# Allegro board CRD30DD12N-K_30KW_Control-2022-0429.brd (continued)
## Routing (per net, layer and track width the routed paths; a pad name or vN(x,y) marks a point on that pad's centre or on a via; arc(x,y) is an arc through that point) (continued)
P_SDA: length 24.7
  ART03 w0.127: v1(63.5,34.29) 62.61,34.29 56.74,40.16 47.2,40.16 v1(46.71,40.64)
  BOTTOM w0.152: U32.5 64.14,33.66 v1(63.5,34.29) 63.5,34.67 64.26,35.44 R437.1 ; U28.173 v1(46.71,40.64)
P_WD_GREEN: length 13.2
  TOP w0.152: D102.2 41.73,43.25 41.02,42.55 v1(40.64,42.55)
  BOTTOM w0.152: v1(40.64,42.55) 40.31,42.87 34.48,42.87 32.55,40.93 32.55,40.46 31.71,39.63 U28.143
P_WD_RED: length 17.2
  TOP w0.152: v1(44.7,42.29) 45.5,42.29 45.72,42.51 D103.2
  BOTTOM w0.152: U28.144 32.22,39.56 33.08,40.42 33.08,40.83 34.51,42.26 39.91,42.26 40.13,42.04 41.55,42.04 42.19,42.67 44.32,42.67 v1(44.7,42.29)
PCS_ADC1: length 11.4
  BOTTOM w0.152: C703.1 R706.2 58.54,24.25 56.05,21.76 52.91,21.76 52.39,22.28 U28.30
RLYCTRL11: length 3.9
  TOP w0.152: v1(28.07,40.64) 27.94,40.51 R703.2
  BOTTOM w0.152: v1(28.07,40.64) 27.69,40.64 26.71,39.67 U28.133
RLYCTRL22: length 38.7
  ART03 w0.127: v1(57.63,30.66) 53.42,30.66 52.7,31.37 52.7,32.13 52.44,32.4 32.37,32.4 v1(28.96,35.81)
  BOTTOM w0.152: v1(57.63,30.66) 57.1,31.19 57.1,32.05 56.77,32.38 R704.2 ; U28.132 26.21,36.79 27.18,35.81 v1(28.96,35.81)
SA_ADC: length 57.8
  TOP w0.152: D124.3 v1(25.4,41.53)
  ART03 w0.127: v1(46.08,19.3) 45.68,19.7 31.06,19.7 29.55,21.21 29.55,33.93 26.92,36.56 26.92,39.12 25.4,40.64 v1(25.4,41.53)
  BOTTOM w0.152: v1(46.08,19.3) 46.08,19.12 48.41,16.79 U28.41 57.47,16.79 57.99,16.26 58.93,16.26 ; R713.2 C706.1 58.93,16.26 ; 58.93,16.26 R712.1
SA_ADC1: length 10.4
  BOTTOM w0.152: U28.40 55.64,17.28 55.64,17.28 57.6,17.28 58.23,17.9 R712.2 C705.1
SB_ADC: length 54.1
  TOP w0.152: R719.2 C708.1 49.41,15.63 R718.1 48.98,15.75 48.78,15.95 48.78,17.68 v1(48.35,18.11) ; D125.3 v1(22.23,41.53)
  ART03 w0.127: v1(22.23,41.53) 22.61,41.15 24.26,41.15 26.49,38.91 26.49,36.59 29.05,34.03 29.05,21.18 31.01,19.22 44.62,19.22 45.18,18.66 47,18.66 47.54,18.11 v1(48.35,18.11)
  BOTTOM w0.152: v1(48.35,18.11) 48.37,18.09 48.37,18.02 48.61,17.79 U28.39
SB_ADC1: length 5
  TOP w0.152: R718.2 C707.1 51.36,17.27 v1(52.12,18.03)
  BOTTOM w0.152: U28.38 51.87,18.28 v1(52.12,18.03)
SC_ADC: length 57.8
  TOP w0.152: R724.1 47.62,14.65 48,15.03 C710.1 R725.2 48,17.64 47.54,18.11 v1(46.09,18.11) ; D126.3 v1(19.05,41.53)
  ART03 w0.127: v1(46.09,18.11) 46.06,18.07 45.04,18.07 44.45,18.67 30.86,18.67 28.51,21.02 28.51,34.17 26.11,36.57 26.11,38.79 24.26,40.64 19.94,40.64 v1(19.05,41.53)
  BOTTOM w0.152: U28.48 46.71,17.63 46.24,18.11 v1(46.09,18.11)
SC_ADC1: length 4.4
  TOP w0.152: R724.2 C709.1 v1(46.35,11.43)
  BOTTOM w0.152: U28.49 46.22,11.57 v1(46.35,11.43)
SCS_A: length 74.7
  TOP w0.635: v1(45.72,52.2) R715.2 R716.2 R714.2 36.32,50.93 J2.2
  ART03 w0.127: v1(61.34,24.13) 61.72,24.51 61.72,26.71 62.74,27.72 62.74,28.96 64.75,30.97 64.75,31.89 70.48,37.63 70.48,40.47 66.46,44.5 53.42,44.5 v1(45.72,52.2)
  BOTTOM w0.152: v1(61.34,24.13) 61.98,23.5 61.98,21.13 62.29,20.82 62.29,19.88 61.48,19.07 61.48,17.39 62.32,16.55 62.32,14.19 61.46,13.34 R713.1
SCS_B: length 102.9
  TOP w0.152: v1(51.82,15) 51.69,14.88 51.69,12.85 51.54,12.7 R719.1
  TOP w0.635: J2.8 26.04,48.27 R722.2 R721.2 R720.2 31.39,45.85 31.9,46.35 v1(32.77,46.35)
  ART03 w0.127: v1(32.77,46.35) 36.4,46.35 38.95,43.8 66.45,43.8 70.1,40.15 70.1,37.83 61.72,29.45 61.72,27.3 61.28,26.86 61.28,24.91 60.82,24.45 60.82,21.59 61.28,21.12 61.93,21.12 63.2,19.84 63.2,11.22 62.18,10.2 56.82,10.2 53.01,14.01 52.81,14.01 v1(51.82,15)
SCS_C: length 89.6
  TOP w0.152: R725.1 v1(45.08,17.14)
  TOP w0.635: v1(62.36,46.23) 63.76,46.23 R728.2 R727.2 R726.2 69.22,47.82 68.59,48.45 68.59,51.44 J3.10
  ART03 w0.127: v1(62.36,46.23) 65.56,46.23 70.99,40.79 70.99,37.67 65.61,32.29 65.61,29.92 62.07,26.38 62.07,22 63.63,20.45 63.63,11.05 62.43,9.85 56.57,9.85 52.83,13.59 42.96,13.59 42.29,14.26 42.29,15.86 43.58,17.14 v1(45.08,17.14)
SCS_RTN_A: length 15.7
  TOP w0.635: R711.1 46.98,48.13 R715.1 R716.1 R714.1 35.06,48.13 J2.4
SCS_RTN_B: length 15.9
  TOP w0.635: R717.1 32.38,43.05 R720.1 R721.1 R722.1 24.98,43.05 24.59,43.43 24.59,49.37 J2.10
SCS_RTN_C: length 19.3
  TOP w0.635: R723.1 62.87,43.05 R728.1 R727.1 R726.1 70.79,43.05 71.29,43.55 71.29,51.28 J3.12
SR-PWM-A: length 42.3
  TOP w0.152: U59.12 63.91,22.23 v1(63.25,22.89)
  ART03 w0.127: v1(63.25,22.89) 62.52,23.61 62.52,26.37 66.63,30.48 66.63,32.83 71.34,37.53 71.34,41.21 65.34,47.21 60.11,47.21 J3.1
SR-PWM-AA: length 45.3
  TOP w0.152: 65.12,23.5 64.54,23.5 63.9,24.14 63.9,25.76 63.12,26.54 58.29,26.54 v1(57.53,25.78) ; R422.2 40.01,42.19 v1(39.47,41.66)
  ART03 w0.127: v1(39.47,41.66) 39.88,41.66 40.64,40.89 40.64,40.13 43.43,37.34 49.02,37.34 50.8,35.56 50.8,34.8 51.94,33.66 52.32,33.66 52.7,33.27 52.7,32.77 53.09,32.38 56.64,32.38 58.17,30.86 58.17,26.42 v1(57.53,25.78)
  BOTTOM w0.152: v1(39.47,41.66) 39.47,40.32 40.22,39.58 U28.160
SR-PWM-B: length 39.9
  TOP w0.152: 59.59,23.5 61.59,23.5 v1(63.25,25.15)
  ART03 w0.127: v1(63.25,25.15) 63.25,26.44 67.58,30.78 67.58,33.26 71.7,37.38 71.7,41.61 65.27,48.04 61.82,48.04 J3.3
SR-PWM-BB: length 40.2
  TOP w0.152: v1(43.69,41.78) 43.31,41.4 43.31,40.26 43.56,40.01 43.56,38.1 43.43,37.98 R423.2 ; v1(59.87,25.91) 60.71,25.91 60.83,25.78 60.83,24.89 60.71,24.77 U59.1
  ART03 w0.127: v1(59.87,25.91) 59.82,25.96 59.82,32 55.5,36.32 52.96,36.32 52.7,36.58 52.7,38.23 52.07,38.86 44.58,38.86 43.05,40.39 43.05,41.15 v1(43.69,41.78)
  BOTTOM w0.152: v1(43.69,41.78) 43.22,41.31 U28.166
SR-PWM-C: length 41
  TOP w0.152: v1(63.25,24.13) 62.74,23.62 62.74,21.59 62.1,20.95 U59.4
  ART03 w0.127: v1(63.25,24.13) 64.77,25.65 64.77,27.36 68.65,31.23 68.65,33.95 72.07,37.38 72.07,42.12 65.31,48.89 63.52,48.89 J3.5
SR-PWM-CC: length 25.5
  TOP w0.152: v1(52.07,36.83) R424.2 ; U59.3 v1(57.91,22.23)
  ART03 w0.127: v1(52.07,36.83) 52.07,36.22 52.73,35.56 55.67,35.56 59.23,32 59.23,23.54 v1(57.91,22.23)
  BOTTOM w0.152: U28.4 50.91,35.28 52.07,36.45 v1(52.07,36.83)
SR-PWM-D: length 41
  TOP w0.152: U59.6 60.81,18.41 60.96,18.57 60.96,18.67 63.5,21.21 v1(63.5,21.59)
  ART03 w0.127: v1(63.5,21.59) 63.87,21.96 63.87,21.98 66.04,24.14 66.04,28.13 69.56,31.65 69.56,34.36 72.46,37.25 72.46,42.49 J3.7
SR-PWM-DD: length 30.5
  TOP w0.152: U59.5 58.29,19.68 57.91,20.07 v1(57.91,21.21) ; R425.2 v1(53.34,33.02)
  ART03 w0.127: v1(53.34,33.02) 56.64,33.02 58.72,30.94 58.72,23.79 57.4,22.48 57.4,21.72 v1(57.91,21.21)
  BOTTOM w0.152: v1(53.34,33.02) 53.34,32.77 52.8,32.23 52.8,26.47 52.47,26.14 51.5,26.14 51.36,26.28 U28.22
SR-PWM-E: length 41.9
  TOP w0.152: v1(66.8,16.26) 66.8,16.76 66.42,17.14 U59.8
  ART03 w0.127: J3.9 72.84,44.64 72.84,33.35 67.35,27.86 67.35,23.92 65.79,22.35 65.79,17.27 v1(66.8,16.26)
SR-PWM-EE: length 30.8
  TOP w0.152: U59.9 62.99,18.41 v1(62.23,17.65) ; R610.2 53.85,31.11 52.7,31.11 v1(51.94,31.88)
  ART03 w0.127: v1(51.94,31.88) 51.82,31.88 50.67,30.73 50.67,29.34 51.41,28.6 52.81,28.6 55.75,25.65 55.75,20.57 57.28,19.05 60.83,19.05 v1(62.23,17.65)
  BOTTOM w0.152: U28.10 51.54,32.28 v1(51.94,31.88)
SR-PWM-F: length 36.2
  TOP w0.152: v1(66.67,19.68) U59.10
  ART03 w0.127: v1(66.67,19.68) 68.56,21.57 68.56,28.39 73.24,33.07 73.24,46.79 J3.11
SR-PWM-FF: length 26.2
  TOP w0.152: v1(51.94,30.79) 51.64,30.48 R611.2 ; U59.11 63.93,20.95 62.23,19.25 v1(62.23,18.8)
  ART03 w0.127: v1(51.94,30.79) 51.31,30.15 51.31,29.59 51.88,29.02 53.02,29.02 56.39,25.65 56.39,21.59 57.53,20.45 60.58,20.45 v1(62.23,18.8)
  BOTTOM w0.152: U28.13 v1(51.94,30.79)
TCK_P: length 8.6
  TOP w0.152: v1(29.86,11.54) 31.87,11.54 33.05,10.36 33.05,9.63 33.66,9.02 R408.2 R407.2
  BOTTOM w0.152: U28.81 30.22,11.82 29.94,11.54 v1(29.86,11.54)
TDI_P: length 18.1
  TOP w0.152: R405.2 v1(29.84,6.35) 29.2,5.7 28.44,5.7 27.92,5.18 27.92,3.2 J5.3
  BOTTOM w0.152: U28.77 32.22,11.36 33.04,10.54 33.04,8.95 32.52,8.44 32.52,6.2 32.14,5.82 30.38,5.82 v1(29.84,6.35)
TDO_P: length 13.9
  TOP w0.152: J5.7 33.01,3.19 33.01,5.09 v1(31.75,6.35) 32.38,6.99 R406.2
  BOTTOM w0.152: U28.78 31.71,6.39 v1(31.75,6.35)
TMS_P: length 15.7
  TOP w0.152: R404.2 v1(26.04,6.35) 25.18,5.5 25.18,3.39 J5.1
  BOTTOM w0.152: v1(26.04,6.35) 29.24,9.56 29.24,10.44 29.67,10.87 30.07,10.87 30.71,11.51 U28.80
VO1+: length 16.3
  BOTTOM w0.508: R574.1 90.05,41.41 J4.1
VO2+: length 11.9
  TOP w0.508: R573.1 88.27,45.73 J4.3
VP3.3A: length 45.8
  TOP w0.381: v1(48.26,19.28) 48.49,19.05 C521.1
  TOP w0.508: C550.2 v1(43.81,15.24) ; D128.2 60.64,6.66 v1(60.33,6.35) ; v1(54.29,6.05) D89.2 ; D127.2 42.86,6.65 42.35,6.15 v1(41.72,6.15)
  ART03 w0.381: v1(34.19,6.25) 35.05,7.11 40.75,7.11 v1(41.72,6.15) 42.5,6.15 43.18,5.46 50.8,5.46 v1(51.44,6.1) 52.11,6.77 53.57,6.77 v1(54.29,6.05)
  BOTTOM w0.254: v1(43.81,15.24) 43.71,15.14 U28.54 ; v1(48.26,19.28) U28.36
  BOTTOM w0.381: v1(34.19,6.25) 33.72,6.25 33.34,6.63 D86.2 ; v1(54.29,6.05) 55.51,4.83 56.44,4.83
  BOTTOM w0.508: v1(41.72,6.15) 40.96,6.9 D90.2 ; v1(51.44,6.1) 51.64,6.1 52.39,6.85 D115.2 ; D85.2 53.66,23.18 v1(52.96,22.48) ; D92.2 v1(57.47,18.1)
  vias: v1(60.83,10.79) v1(61.85,10.79)
VP3.3D: length 171.2
  TOP w0.152: D104.2 49.53,43.18
  TOP w0.381: v1(26.67,16.51) 26.67,16.63 C540.1 ; R411.1 R412.1 47.11,2.03 48.39,0.76 63.88,0.76 ; v1(26.35,40.64) D124.2 ; C541.2 v1(27.94,15.24) ; D95.2 v1(16.82,39.5) ; D126.2 v1(20,39.5) ; D125.2 v1(23.17,39.5)
  TOP w0.508: C542.2 v1(29.84,15.24) ; C536.1 v1(26.67,28.57) ; v1(44.2,36.83) 44.32,36.96 C523.2 ; C552.1 C557.2 v1(48.26,24.13) ; 49.53,43.18 v1(49.53,41.91) v1(51.44,41.91) 50.92,41.4 C520.1 ; C534.1 v1(26.67,31.11) ; v1(39.37,15.24) 38.61,15.24 38.23,14.86 C547.2 ; C555.2 v1(48.26,27.94) ; C553.2 49.28,33.02 48.26,32 v1(48.26,31.75) ; C524.2 v1(40.01,36.83) ; v1(12.24,30.89) 12.7,31.35 R691.1 R537.2 ; R327.2 v1(31.75,40.64) ; R409.2 v1(31.11,10.16) ; C528.2 v1(33.66,36.83) ; C539.1 v1(26.67,20.32) ; C544.2 v1(33.66,15.24) ; v1(29.59,36.83) 30.48,37.72 C529.2 ; J17.2 77.91,8.41 R598.1 ; C538.1 v1(26.67,23.5) ; v1(36.2,10.16) 35.94,9.91 35.94,8 35.43,7.5 R407.1 ; C533.1 26.16,32.38 v1(26.67,32.89) ; C545.2 v1(34.92,15.24) ; C546.2 v1(36.83,15.24) ; R404.1 v1(26.04,10.16) ; R406.1 v1(32.38,10.16) ; C537.1 v1(26.67,27.3) ; v1(34.92,36.83) C527.2 ; C531.1 v1(26.67,34.92) ; R405.1 v1(29.84,10.16) ; R400.2 v1(37.47,40.64) ; R540.1 5.59,21.82
  ART03 w0.508: v1(26.35,40.64) 26.35,42.55 ; v1(4.19,47.62) 7.38,44.43 7.38,39.35 10.72,36.02 10.72,33.26 12.24,31.74 v1(12.24,30.89)
  BOTTOM w0.254: v1(26.67,27.3) 26.19,27.79 U28.114 ; U28.127 26.03,34.28 v1(26.67,34.92) ; 48.26,29.79 U28.15 ; v1(33.66,15.24) 33.22,14.8 U28.75 ; U28.26 48.41,24.28 v1(48.26,24.13) ; U28.68 36.71,15.12 v1(36.83,15.24) ; U28.159 39.71,37.12 v1(40.01,36.83) ; U28.91 26.44,16.28 v1(26.67,16.51) ; U28.119 26.22,30.28 26.67,30.73 v1(26.67,31.11) 26.04,31.11 25.71,30.79 U28.120 ; U28.11 48.3,31.79 v1(48.26,31.75) ; U28.3 48.49,35.79 ; U28.106 26.38,23.79 v1(26.67,23.5) ; U28.116 26.46,28.79 v1(26.67,28.57) ; U28.125 26.28,33.28 v1(26.67,32.89) ; v1(34.92,36.83) 35.23,36.83 36.22,37.82 U28.152 ; v1(34.92,15.24) 34.71,15.03 U28.72 ; v1(48.26,27.94) 48.92,27.28 U28.20 ; v1(26.67,15.24) 26.71,15.2 U28.88 ; v1(29.84,15.24) 29.71,15.11 U28.82 ; v1(33.66,36.83) 33.71,36.89 U28.147 ; v1(44.2,36.83) 44.22,36.85 U28.168 ; v1(39.37,15.24) 39.71,14.9 U28.62 ; U28.99 26.63,20.28 v1(26.67,20.32) ; U28.138 29.22,37.21 v1(29.59,36.83)
  BOTTOM w0.381: v1(19.18,27.94) R546.2
  BOTTOM w0.508: J17.2 78.11,8.22 C405.1 ; R437.2 R438.2 v1(66.67,38.1) ; v1(71.37,33.02) 72.01,32.38 R505.1 ; v1(67.94,38.1) 67.94,37.59 R439.2 ; v1(71.37,34.29) 71.88,34.29 R502.1 ; v1(70.8,29.81) 70.8,29.94 70.14,30.6 C396.1 68.96,30.6 67.94,31.62 67.94,33.18
  vias: v1(3.17,47.62) v1(3.17,46.35) v1(3.17,45.09) v1(3.17,43.81) v1(5.43,21.66) v1(6.35,11.43) v1(6.35,10.16) v1(6.35,8.89) v1(7.62,11.43) v1(7.62,10.16) v1(7.62,8.89) v1(27.94,16.51) v1(29.84,16.51) v1(52.7,41.91) v1(53.98,41.91) v1(66.04,5.08) v1(67.31,5.08) v1(68.58,5.08) v1(69.85,5.08) v1(71.75,1.27) v1(73.03,1.27) v1(74.3,1.27)
VP+5V: length 55.3
  TOP w0.381: v1(69.22,26.42) 68.58,27.05 56.58,27.05 55.88,26.35 U55.1 53.66,26.35 53.34,26.67 53.34,27.56 53.72,27.94 C494.1 ; R549.2 v1(70.48,33.02)
  TOP w0.508: R536.2 9.01,30.86 v1(9.02,30.86) ; R550.2 69.34,26.29 v1(69.22,26.42)
  ART03 w0.508: 77.35,9.78 77.35,24.94 75.01,27.28 v1(72.27,27.28)
  BOTTOM w0.508: v1(69.22,26.42) 69.85,25.78 R595.2 70.87,25.52 71.38,26.04 R594.2 v1(72.27,27.28) 72.27,29.57 71.18,30.65 71.18,32.08 70.48,32.77 v1(70.48,33.02)
  vias: v1(6.1,32.77) v1(6.1,31.62) v1(6.1,30.48) v1(7.74,30.86) v1(10.29,30.86) v1(11.3,30.86) v1(52.7,5.08) v1(53.98,5.08) v1(53.98,3.81)
VS+5V: length 42.7
  TOP w0.508: v1(95.89,23.75) 95.89,23.6 95.4,23.12 R493.1 ; R496.1 v1(92.59,34.42) ; R507.1 v1(97.91,32.26) ; v1(98.3,23.75) 97.91,24.13 R492.2
  ART03 w0.508: v1(91.56,38.1) 91.56,40.22 96.45,45.11 96.45,52.76 95.19,54.02 85.13,54.02 J4.4
  BOTTOM w0.508: v1(92.71,32.38) 92.08,33.02 R503.1 ; R569.1 v1(88.9,35.56) ; R500.1 v1(91.56,38.1) R597.1 ; R593.2 91.87,26.04 v1(92.53,26.7) ; R592.2 v1(88.9,20.95)
XCLK: length 4.6
  TOP w0.152: Y3.3 21.68,32.35 C712.1 22.86,32.38 v1(22.86,32.38)
  BOTTOM w0.254: v1(22.86,32.38) 22.96,32.28 U28.123
XRS: length 22.3
  TOP w0.381: v1(15.49,29.84) 11.68,29.84 10.92,29.08 R547.1
  TOP w0.508: R541.1 10.29,23.5 10.29,24.43 11.18,25.32 11.18,27.74 10.92,28 R547.1
  BOTTOM w0.254: C519.1 23.5,33.02 23.73,32.79 U28.124
  BOTTOM w0.381: C519.1 21.08,33.02 R546.1 17.53,33.02 15.49,30.99 v1(15.49,29.84)
N16779815: length 3.9
  TOP w0.152: R327.1 31.75,37.92 v1(30.66,36.83)
  BOTTOM w0.152: v1(30.66,36.83) 29.71,37.77 U28.139
N16833081: length 2
  TOP w0.152: R443.1 43.57,45.45 D102.1
N16833084: length 2
  TOP w0.152: D103.1 47.28,45.55 R444.1
N16833087: length 2
  TOP w0.152: D104.1 51.09,45.55 R445.1
N16835391: length 39
  TOP w0.152: v1(68.58,12.7) 73.03,8.26 J17.1
  BOTTOM w0.152: R447.1 59.05,28.2 62.7,24.55 62.7,21.5 63.32,20.88 63.32,16.27 63.91,15.68 67.5,15.68 68.58,14.61 v1(68.58,12.7) ; R446.1 C407.1 J17.1
N16848574: length 4.1
  BOTTOM w0.508: U43.2 88.01,24.77 88.14,24.64 89.92,24.64 R482.2 C446.1
N16848598: length 4.6
  BOTTOM w0.381: R593.1 C445.2
  BOTTOM w0.508: C445.2 89.41,27.3 88.14,26.04 U43.1
N16848614: length 4.9
  TOP w0.508: v1(74.93,25.4) 75.44,24.89 C447.2
  BOTTOM w0.152: U43.8 75.39,26.04 74.93,25.58 v1(74.93,25.4) 74.3,26.04 R594.1
N16848642: length 2.8
  BOTTOM w0.152: R483.1 U43.7
N16848644: length 15.1
  TOP w0.152: v1(71.12,21.08) 71.12,19.68 67.18,15.75 65.91,15.75 v1(65.41,16.26)
  BOTTOM w0.152: v1(65.41,16.26) U45.3 ; v1(71.12,21.08) 72.26,22.23 C448.2 R484.2 R483.2
N16848814: length 4.9
  BOTTOM w0.152: R485.1 74.52,20.95 74.68,21.11 74.68,22.99 75.18,23.5 76.54,23.5
N16848816: length 8.1
  BOTTOM w0.152: R485.2 72.27,19.61 71.83,19.17 R486.1 C449.1 69.22,19.17 68.98,19.42 67.17,19.42 66.67,18.92 U45.2
N16848832: length 28.9
  TOP w0.152: v1(54.86,8.94) 54.86,8.52 55.25,8.13 R487.1
  ART03 w0.127: v1(54.86,8.94) 54.95,8.94 55.04,8.86 67.24,8.86 70.48,12.1 70.48,15.88 v1(69.85,16.51)
  BOTTOM w0.152: 67.94,18.25 67.94,17.23 68.67,16.51 v1(69.85,16.51) C449.2 R486.2
N16848970: length 3.4
  BOTTOM w0.152: U44.7 95.25,20.45 95.5,20.19 96.22,20.19 96.52,20.5 U44.6
N16848978: length 9.7
  TOP w0.152: C454.1 R488.2 C453.2 R489.2 R492.1 96.4,24.25 v1(96.9,23.75)
  BOTTOM w0.152: U44.3 96.52,24.03 96.8,23.75 v1(96.9,23.75)
N16848994: length 10.6
  TOP w0.152: R493.2 R494.2 ; R494.2 93.07,24.64 v1(92.71,24.99) 91.97,24.25 R491.1 C455.1 ; R494.2 93.47,24.76 C454.2
  BOTTOM w0.152: v1(92.71,24.99) 94.59,24.99 95.25,25.66 U44.2
N16849016: length 4.4
  BOTTOM w0.152: U44.8 93.98,22.07 93.83,22.23 C457.1 R592.1
N16851028: length 3.3
  BOTTOM w0.152: U45.7 66.67,24.61 66.52,24.77 65.56,24.77 65.41,24.61 U45.6
N16851046: length 4.3
  BOTTOM w0.152: C451.1 R595.1 69.21,24.01 68.83,24.38 68.2,24.38 67.94,24.13 67.94,23.66
N16853569: length 5.3
  TOP w0.152: v1(95.89,34.29) 95.76,34.41 R495.2 C458.1 C460.1
  BOTTOM w0.152: U48.3 v1(95.89,34.29)
N16853931: length 10.1
  TOP w0.152: C460.2 97.28,38.61 96.82,39.07 94.51,39.07 94.1,38.66 R497.1 C459.1 R496.2 94.1,34.8 v1(94.61,34.29)
  BOTTOM w0.152: U48.2 v1(94.61,34.29)
N16853972: length 12.8
  TOP w0.152: C714.2 89.41,30.99 88.65,30.99 88.27,31.37 88.27,33.66 v1(88.9,34.29)
  BOTTOM w0.152: U48.1 93.18,35.56 R569.2 91.56,35.05 90.81,34.29 v1(88.9,34.29) 88.27,33.66 86.94,33.66
N16854025: length 16.8
  ART03 w0.508: v1(90.17,38.1) 87.76,35.69 87.76,30.86 v1(88.9,29.72)
  BOTTOM w0.508: R597.2 90.05,38.22 v1(90.17,38.1) ; v1(88.9,29.72) 89.28,30.1 C462.1 C566.1 91.44,30.1 92.08,29.46 93.09,29.46 93.34,29.72 U48.8
N16854569: length 3.4
  BOTTOM w0.152: U60.1 88.39,36.2 89.03,36.83 R500.2
N16855013: length 10.3
  TOP w0.152: R508.1 C467.1 R507.2 96.4,32.26 v1(96.39,32.26) 95.89,32.77 94.23,32.77 93.47,32.01 C466.2
  BOTTOM w0.152: U48.5 97.16,31.5 v1(96.39,32.26)
N16855828: length 6
  TOP w0.152: v1(95.38,32.26) 94.99,31.87 C466.1 C465.1 R506.2
  BOTTOM w0.152: v1(95.38,32.26) 95.89,31.75 U48.6
N16855912: length 12.8
  TOP w0.152: v1(88.9,28.57) 91.19,30.86 C713.2
  BOTTOM w0.152: U48.7 94.61,29.34 93.85,28.57 v1(88.9,28.57) U61.2
N16855916: length 4.6
  BOTTOM w0.152: R503.2 88.9,33.02 88.39,32.51 88.39,31.37 88.14,31.11 U61.1
N16860426: length 84.1
  TOP w0.152: C471.1 C472.1 ; C472.1 R598.2 ; C472.1 75.63,13.34 v1(75.25,12.95)
  ART03 w0.127: v1(18.41,24.13) 18.41,17.02 25.91,9.53 36.32,9.53 37.37,10.57 37.37,11.59 38.25,12.47 52.11,12.47 53.12,11.47 53.12,9.84 55.26,7.7 61.87,7.7 62.31,8.14 70.44,8.14 v1(75.25,12.95)
  BOTTOM w0.152: U53.1 75.44,11.43 75.25,11.62 v1(75.25,12.95) ; R515.1 R514.1 v1(18.41,24.13)
N16860580: length 10.1
  TOP w0.508: v1(91.44,11.56) 91.31,11.56 90.83,12.04 90.32,12.04 R516.2 C474.1 C475.1 C473.1
  BOTTOM w0.508: v1(91.44,11.56) 91.31,11.43 U53.8
N16860640: length 8.9
  TOP w0.152: v1(84.45,13.97) D110.2 D112.1
  BOTTOM w0.152: T1.2 90.08,13.97 U53.7 v1(84.45,13.97)
N16861373: length 4.3
  TOP w0.381: D111.2 90.77,14.61 90.3,14.61 89.66,15.24 D112.2 D114.2
N16861380: length 9
  TOP w0.152: v1(84.45,16.51) D114.1 D113.2
  BOTTOM w0.152: v1(84.45,16.51) U53.6 90.08,16.51 T1.1
N16900365: length 4
  TOP w0.508: R537.1 R538.2 8.55,33.78 7.93,34.39 Q1.1
N16900541: length 7.3
  TOP w0.508: v1(8.4,27.46) 8.4,27.92 C505.1 7.5,28.82 R536.1 6.99,30.36 Q1.3
  BOTTOM w0.381: v1(8.4,27.46) 8.58,27.64 U57.7
N16908509: length 4.6
  TOP w0.508: v1(7.75,24.51) 7.41,24.51 7.11,24.2 R540.2 R541.2
  BOTTOM w0.381: v1(7.75,24.51) 7.93,24.33 U57.19
N16935004: length 2.7
  TOP w0.508: v1(9.41,27.47) 9.4,27.48 R547.2
  BOTTOM w0.381: v1(9.41,27.47) 9.23,27.65 U57.8
N17022031: length 6.6
  TOP w0.152: U58.14 C560.1 C562.1 R549.1 C561.1
N17025421: length 6.5
  TOP w0.152: U59.14 R550.1 C563.1 C565.1 C564.1
N17096901: length 15.4
  TOP w0.381: R573.2 87.63,36.7 87.63,28.57 88.78,27.43 R133.1 C237.2 91.55,27.32 93.46,27.32 R488.1
N17102058: length 20.3
  TOP w0.152: v1(98.42,35.56) R495.1 96.93,35.21 96.93,35.08 96.52,34.67 96.52,34.08 96.52,34.08 96.52,33.91 96.06,33.45 92.86,33.45 91.95,32.54 91.95,29.49 92.86,28.57 R506.1
  BOTTOM w0.152: R574.2 93.99,38.61 C594.1 R575.1 97.69,38.61 97.92,38.38 97.92,36.07 v1(98.42,35.56)
N17145229: length 14.1
  BOTTOM w0.152: U28.57 42.22,12.12 42.04,11.94 42.04,10.79 42.55,10.29 42.55,8.49 42.12,8.07 42.12,6.68 43.03,5.77 45.46,5.77 45.84,6.15 C595.1 R599.2
N17182974: length 95
  TOP w0.152: R528.1 C488.1 R58.2 52.45,12.58 v1(51.31,11.43) 51.31,11.31 R529.1
  ART03 w0.127: v1(5.71,50.17) 5.71,50.16 8.17,47.71 8.17,39.33 9.02,38.48 11.68,38.48 12.18,37.98 12.18,33.84 13.08,32.94 13.08,15.34 16.93,11.49 21.58,11.49 25.07,8 37.02,8 38.9,9.89 38.9,10.16 39.28,10.53 41.53,10.53 42.09,9.97 43.19,9.97 46.9,6.27 48.05,6.27 51.31,9.52 v1(51.31,11.43)
  BOTTOM w0.152: v1(5.71,50.17) 4.95,49.41 R49.1
N17183073: length 4.3
  TOP w0.152: R534.1 R532.2 53.98,20.95 54.49,20.44 C492.1 R533.1
N17183105: length 2.3
  TOP w0.152: U55.2 53.66,24.45 53.47,24.26 53.47,23.49 R532.1
N17213567: length 8.8
  BOTTOM w0.152: R729.2 54.74,26.92 R730.2 53.82,26.67 53.06,25.9 53.06,23.85 52,22.79 U28.29
N17215412: length 16.8
  BOTTOM w0.152: U28.42 56.11,16.28 57.55,14.84 57.55,13.47 58.57,12.45 61.74,12.45 63.32,14.03 63.32,14.55 R679.1
N17215422: length 5.1
  BOTTOM w0.152: U28.43 51.09,15.79 51.22,15.92 52.99,15.92 53.35,15.55 53.35,14.74 R678.1
N17215466: length 5.1
  BOTTOM w0.152: C691.2 R681.2 64.77,14.48 R679.2 66.04,14.61 DAC_5.1
N17215490: length 4.7
  BOTTOM w0.152: R678.2 C690.2 R680.2 56.64,12.58 DAC_4.1
N17215663: length 9.7
  BOTTOM w0.152: 47.63,7.63 DAC_1.1 ; 47.63,7.63 47.63,10.32 47.22,10.73 U28.47 ; 47.63,7.63 49.02,9.01 C687.2 R673.2
N17215880: length 6.3
  TOP w0.152: R607.2 C598.1 53.71,16 v1(52.79,15.08)
  BOTTOM w0.152: v1(52.79,15.08) 52.32,15.54 51.51,15.54 51.25,15.28 U28.44
N17228521: length 64.1
  TOP w0.152: R693.1 38.56,7.5 38.81,7.75 38.81,9.6 39.2,9.99 39.61,9.99 v1(39.62,10.01)
  ART03 w0.127: v1(11.44,37.9) 11.44,33.59 12.77,32.26 12.77,14.82 16.8,10.79 21.34,10.79 24.52,7.62 37.24,7.62 v1(39.62,10.01)
  BOTTOM w0.635: R692.1 C698.1 R695.2 12.69,37.97 11.58,37.97 11.5,37.9 v1(11.44,37.9) 11.37,37.97 R694.1
N17284506: length 9.4
  TOP w0.152: J5.11 J5.9 35.54,3.19 35.54,5.61 R408.1
N17284677: length 6.4
  TOP w0.152: J5.5 30.5,3.15 30.5,6.3 31.11,6.91 R409.1
N17284729: length 3.9
  TOP w0.152: J5.13 42.55,2.54 R412.2
N17284735: length 3.9
  TOP w0.152: R411.2 42.55,3.81 J5.14
N17302767: length 7
  BOTTOM w0.152: T2.3 95.18,13.27 93.22,11.31 R517.2 93.22,8.77 J11.1
N17302775: length 8.3
  BOTTOM w0.152: J11.2 94.74,8.73 R517.1 96.01,12.06 98.51,12.06 98.66,12.22 T2.4
N17302818: length 6.4
  BOTTOM w0.152: T1.3 94.66,14.35 94.87,14.35 95.76,15.24 97.41,15.24 98.66,16.49 T2.1
N17302820: length 2.7
  BOTTOM w0.152: T2.2 96.16,16.66 95.99,16.49 T1.4
N17326807: length 5.7
  TOP w0.152: Y3.4 18.71,32.35 19.3,31.75 19.3,30.35 C711.1 17.29,29.46 R731.1
N16779431153: length 3.1
  TOP w0.152: R400.1 v1(37.47,36.83)
  BOTTOM w0.152: U28.154 37.22,37.08 v1(37.47,36.83)

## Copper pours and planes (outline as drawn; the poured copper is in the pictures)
AGND on TOP (solid shape): 43.45,29.63 43.45,24.1 41.65,22.3 38.9,22.3 37.89,21.29 33.32,21.29 31.64,22.97 31.64,31.9 32.32,32.58 40.5,32.58
AGND on TOP (solid shape): outline of 101 points within 0.59,0.57 29.16,18.06
AGND on TOP (solid shape): outline of 166 points within 11.56,22.99 22.99,29.34
AGND on BOTTOM (solid shape): 43.19,31.06 43.19,21.89 42.1,20.8 32.22,20.8 31.23,21.79 31.23,31.28 31.85,31.9 42.35,31.9
AGND on BOTTOM (solid shape): 53.94,2.79 53.94,0.69 53.81,0.56 45.01,0.56 44.86,0.71 44.86,1.77 45.02,1.93 48.44,1.93 48.86,1.51 52.06,1.51 52.39,1.84 52.39,2.83 52.53,2.97 53.76,2.97
AGND on BOTTOM (solid shape): 61.82,2.52 65.34,2.52 65.68,2.86 70.05,2.86 70.24,2.66 70.24,1.12 69.94,0.82 56.94,0.82 56.65,1.11 56.65,2.28 56.87,2.5 58.86,2.5 59.22,2.86 61.48,2.86
AGND on BOTTOM (solid shape): 82.1,19.81 82.1,0.85 81.82,0.57 75.45,0.57 75.26,0.76 75.26,1.38 75.55,1.66 78.71,1.66 79.62,2.57 79.62,10.76 78.92,11.46 78.92,19.73 79.18,19.99 81.92,19.99
AGND on BOTTOM (solid shape): outline of 279 points within 0.56,3.81 23.62,37.77
AGND on ART02 (solid shape): outline of 14876 points within 0.56,0.56 81.28,54.44
AGND on ART03 (solid shape): 44.15,29.09 44.15,21.17 43.5,20.53 31.2,20.53 30.65,21.08 30.65,30.15 31.44,30.94 42.29,30.94
AGND on ART03 (solid shape): outline of 121 points within 14.5,13.55 19.52,37.59
SGND on TOP (solid shape): outline of 214 points within 85.9,19.97 99.44,41.16
SGND on BOTTOM (solid shape): outline of 223 points within 95.38,22.39 99.43,42.2
SGND on ART02 (solid shape): outline of 1737 points within 80.48,19.94 99.44,54.44
VDD on TOP (solid shape): outline of 375 points within 7.66,3.28 48.64,37.21
VDD on BOTTOM (solid shape): 10.12,23.98 10.29,23.95 10.46,23.98 11.21,23.98 11.37,23.82 11.37,21.29 10.73,20.65 10.73,6.14 11.07,5.8 11.07,4.09 10.88,3.9 7.96,3.9 7.81,4.05 7.81,5.82 8.89,6.9 8.89,21.15 9.7,21.96 9.7,23.75 9.92,23.98
CAN5V_GND on TOP (solid shape): outline of 119 points within 85.98,0.61 99.44,19.4
CAN5V_GND on BOTTOM (solid shape): 99.44,0.56 89.53,0.56 89.53,1.12 89.49,1.17 89.49,7.37 88.72,8.15 86.32,8.15 85.98,8.48 85.98,10.21 86.32,10.55 90.37,10.55 91.47,9.44 91.47,7.19 91.77,6.9 96.23,6.9 96.53,7.19 96.53,11.56 99.44,11.56
CAN5V_GND on ART02 (solid shape): outline of 329 points within 83.4,0.56 99.44,19.43
CAN5V_GND on ART03 (solid shape): outline of 325 points within 83.41,0.59 99.4,19.38
P_ADREF3.2V on TOP (solid shape): outline of 427 points within 40.13,3.56 50.8,21.66
P_ADREF3.2V on BOTTOM (solid shape): 51.75,5.32 51.75,2.16 51.63,2.03 49.24,2.03 48.61,2.66 48.61,5.37 48.73,5.49 51.59,5.49
VP3.3A on ART03 (solid shape): outline of 578 points within 43.48,10.52 62.89,22.91
VP3.3D on TOP (solid shape): outline of 114 points within 11.05,30.35 17.4,32.89
VP3.3D on TOP (solid shape): outline of 804 points within 48.64,0.63 79.5,42.48
VP3.3D on TOP (solid shape): outline of 991 points within 0.56,8.13 31.89,54.44
VP3.3D on BOTTOM (solid shape): 74.68,5.72 74.68,1.08 74.5,0.9 70.89,0.9 70.74,1.05 70.74,3.02 70.27,3.49 65.6,3.49 65.25,3.14 64.11,3.14 64.03,3.21 64.03,4.32 64.03,5.66 64.03,5.66 64.03,5.92 64.11,6 74.4,6
VP3.3D on BOTTOM (solid shape): outline of 332 points within 1.02,0.69 48.9,37.32
VP3.3D on BOTTOM (solid shape): outline of 780 points within 2.68,38.1 54.61,48.14
VP3.3D on ART03 (solid shape): outline of 1691 points within 15.91,9.84 39.91,44.29
VP+5V on BOTTOM (solid shape): 54.57,5.12 54.57,3.68 54.28,3.4 52.5,3.4 52.49,3.41 52.49,5.33 52.59,5.43 54.26,5.43
VP+5V on BOTTOM (solid shape): 12.06,32.94 12.23,32.94 12.38,32.79 12.38,31.74 12.06,31.42 11.84,31.29 11.7,31.06 11.66,31.02 11.66,30.77 11.38,30.48 11.38,28.27 11.21,28.1 10.53,28.1 10.35,28.27 10.35,30.2 9.99,30.56 6.5,30.56 6.16,30.21 6.16,28.21 6.1,28.15 5.24,28.15 5.15,28.24 5.15,30.23 4.83,30.56 2.9,30.56 2.69,30.76 2.69,32.61 3.03,32.95 12.05,32.95
VP+5V on ART03 (solid shape): outline of 4806 points within 0.56,0.56 82.23,54.44
VS+5V on ART03 (solid shape): outline of 894 points within 88.27,20.33 99.42,38.73
N16830570 on BOTTOM (solid shape): 47.92,5.33 47.92,2.88 47.71,2.66 45.17,2.66 44.81,3.03 44.81,4.22 46.05,5.46 47.8,5.46

Small or netless copper shapes (teardrops, artwork), in the pictures only: 1 on BOTTOM

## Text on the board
BOTTOM: ARTWORK BOTTOM
Board Geometry/Soldermask Bottom: SOLDERMASK BOTTOM
Package Geometry/Pastemask Bottom: PASTEMASK BOTTOM
Ref Des/Silkscreen Bottom: A | B | SILKSCREEN BOTTOM
TOP: ARTWORK TOP
Board Geometry/Soldermask Top: SOLDERMASK TOP
Package Geometry/Pastemask Top: PASTEMASK TOP
Ref Des/Silkscreen Top: C | B | A | CRD30DD12N_30KW_DCDC | RevC 1821 | SILKSCREEN TOP | - | +
ART02: ARTWORK LAYER02
ART03: ARTWORK LAYER03
DIMENSION: Board cut out | Board Cut Out
ASSEMBLY_TOP: PRIMARY SIDE
ASSEMBLY_BOTTOM: SECONDARY SIDE
User.7: ARTWORK LAYER03
User.9: ARTWORK LAYER02
User.22: FIGURE | SIZE | 12.0 | 35.0 | 39.0 | 40.0 | 45.0 | DRILL CHART: TOP to BOTTOM | ALL UNITS ARE IN MILS | PLATED | QTY | 474 | 4 | 48 | 3 | 14
